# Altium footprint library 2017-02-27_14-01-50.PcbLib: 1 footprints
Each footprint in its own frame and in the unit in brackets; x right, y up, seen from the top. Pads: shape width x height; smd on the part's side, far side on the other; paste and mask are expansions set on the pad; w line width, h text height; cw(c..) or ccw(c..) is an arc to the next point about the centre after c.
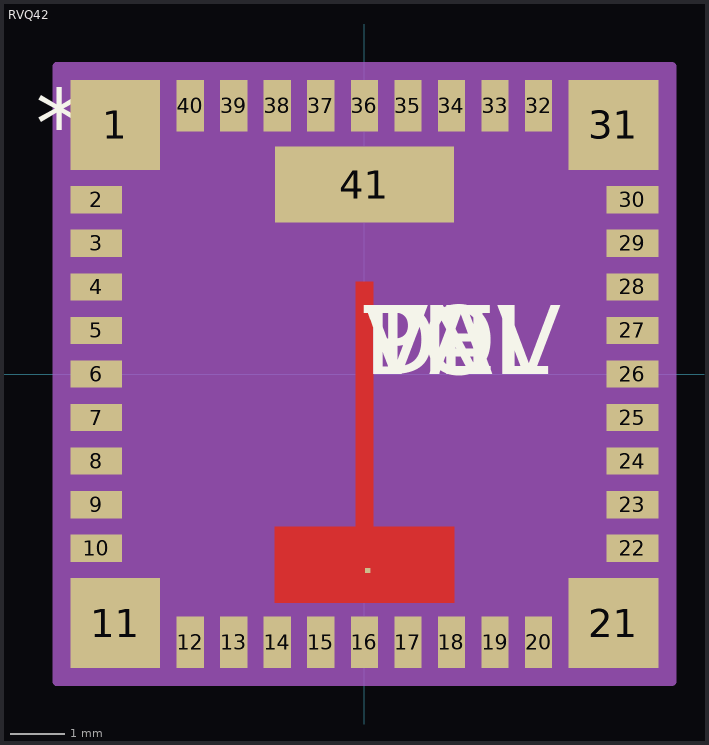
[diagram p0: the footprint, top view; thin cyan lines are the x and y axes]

## RVQ42 [mm]
pads (42):
  rect 1.65x1.65 / inner round 1.524 / far side round 1.524 all layers, no hole: 1(-4.575,4.575) 11(-4.575,-4.575) 21(4.575,-4.575) 31(4.575,4.575)
  rect 0.95x0.5 smd paste-0.25: 2(-4.925,3.2) 3(-4.925,2.4) 4(-4.925,1.6) 5(-4.925,0.8) 6(-4.925,0) 7(-4.925,-0.8) 8(-4.925,-1.6) 9(-4.925,-2.4) 10(-4.925,-3.2) 22(4.925,-3.2) 23(4.925,-2.4) 24(4.925,-1.6) 25(4.925,-0.8) 26(4.925,0) 27(4.925,0.8) 28(4.925,1.6) 29(4.925,2.4) 30(4.925,3.2)
  rect 0.5x0.95 smd paste-0.25: 12(-3.2,-4.925) 13(-2.4,-4.925) 14(-1.6,-4.925) 15(-0.8,-4.925) 16(0,-4.925) 17(0.8,-4.925) 18(1.6,-4.925) 19(2.4,-4.925) 20(3.2,-4.925) 32(3.2,4.925) 33(2.4,4.925) 34(1.6,4.925) 35(0.8,4.925) 36(0,4.925) 37(-0.8,4.925) 38(-1.6,4.925) 39(-2.4,4.925) 40(-3.2,4.925)
  rect 3.29x1.4 smd paste-1.632: 41(0,3.48)
  rect 0.1x0.1 smd paste-0.037: 42(0.066,-3.609)
Top Layer:
  region: -1.595,-4.201 -1.648,-4.201 -1.648,-2.801 -0.16,-2.801 -0.16,1.696 0.16,1.696 0.16,-2.801 1.648,-2.801 1.648,-4.201
Top Overlay:
  text "*" at -6.035,3.981 h1.27
  text "PN" at 0,0 h1.27
  text "DEV" at 0,0 h1.27
  text "VAL" at 0,0 h1.27
  text "TOL" at 0,0 h1.27
Top Paste:
  drawing of 48 lines, arcs and shapes, not listed
Top Solder:
  drawing of 41 lines, arcs and shapes, not listed
Mechanical 13:
  text "*" at -6.035,3.981 h1.27
  text "RefDes2" at 0,0 h1.27
Mechanical 15:
  region: 5.654,-5.654 -5.654,-5.654 -5.654,5.654 5.654,5.654
  lines w0.152: -5.654,-5.654 -5.654,5.654 5.654,5.654 5.654,-5.654 -5.654,-5.654
Mechanical 16:
  circle w0.152: c1.24,-2.501 r0.076
  circle w0.152: c-0.46,1.399 r0.076
  circle w0.152: c-0.46,-2.501 r0.076
  circle w0.152: c-1.24,-2.501 r0.076
  circle w0.152: c0.46,-2.501 r0.076
  circle w0.152: c-0.46,-1.721 r0.076
  circle w0.152: c-0.46,-0.941 r0.076
  circle w0.152: c-0.46,-0.161 r0.076
  circle w0.152: c-0.46,0.593 r0.076
  circle w0.152: c0.46,-1.721 r0.076
  circle w0.152: c0.46,-0.941 r0.076
  circle w0.152: c0.46,-0.161 r0.076
  circle w0.152: c0.46,0.593 r0.076
  circle w0.152: c0.46,1.399 r0.076
3D body: height 0.25, standoff 0, extent 0,0 0.254,0.254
